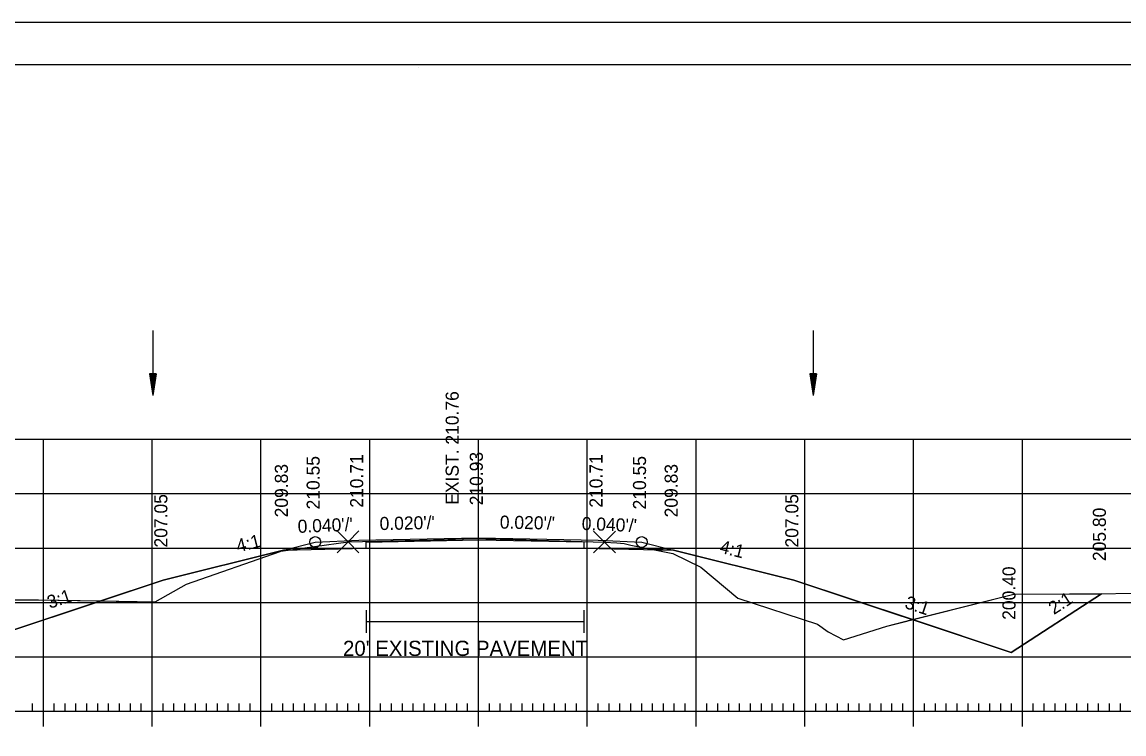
# Model space of a CAD drawing. Extents: x 1312042 to 1371461, y 379929 to 1834241.
# Drawn here: x 1371256.3 to 1371357.6, y 380076.8 to 380142.3 of the extents above; entities that cross this region are included whole.
import ezdxf

# ---------------------------------------------------------------- set-up
doc = ezdxf.new("R2010")
doc.units = 0
for name, color, linetype in [('Default', 7, 'Continuous'), ('R_Alt Surface', 7, 'Continuous'), ('R_Axis', 7, 'Continuous'), ('R_Axis Annot', 7, 'Continuous'), ('R_Border', 7, 'Continuous'), ('R_Exist Surface', 7, 'Continuous'), ('R_Fin Surface', 7, 'Continuous'), ('R_Grid', 7, 'Continuous'), ('R_No Plot', 7, 'Continuous'), ('R_Water Annot', 7, 'Continuous'), ('R_Xsect Elev', 7, 'Continuous'), ('R_Xsect Slope', 7, 'Continuous')]:
    doc.layers.add(name, color=color, linetype=linetype)

msp = doc.modelspace()

# ---------------------------------------------------------------- linework, layer by layer
at = {"layer": 'Default'}
for p, q in [((1371287.96, 380088.19), (1371287.96, 380086.13)), ((1371307.96, 380088.19), (1371307.96, 380086.13)), ((1371287.96, 380087.16), (1371307.96, 380087.16))]:
    msp.add_line(p, q, dxfattribs=at)
at = {"layer": 'R_Alt Surface'}
msp.add_lwpolyline([(1371280.36, 380093.73), (1371287.96, 380093.89), (1371287.96, 380094.45), (1371298.28, 380094.68), (1371307.96, 380094.47), (1371307.96, 380093.9), (1371316.19, 380093.73)], dxfattribs=at)
at = {"layer": 'R_Axis'}
for p, q in [((1371258.28, 380077.51), (1371258.28, 380080.31)), ((1371268.28, 380077.51), (1371268.28, 380080.31)), ((1371278.28, 380077.51), (1371278.28, 380080.31)), ((1371288.28, 380077.51), (1371288.28, 380080.31)), ((1371298.28, 380077.51), (1371298.28, 380080.31)), ((1371308.28, 380077.51), (1371308.28, 380080.31)), ((1371318.28, 380077.51), (1371318.28, 380080.31)), ((1371328.28, 380077.51), (1371328.28, 380080.31)), ((1371338.28, 380077.51), (1371338.28, 380080.31)), ((1371348.28, 380077.51), (1371348.28, 380080.31)), ((1371158.28, 380078.91), (1371438.28, 380078.91)), ((1371257.28, 380078.91), (1371257.28, 380079.61)), ((1371259.28, 380078.91), (1371259.28, 380079.61)), ((1371260.28, 380078.91), (1371260.28, 380079.61)), ((1371261.28, 380078.91), (1371261.28, 380079.61)), ((1371262.28, 380078.91), (1371262.28, 380079.61)), ((1371263.28, 380078.91), (1371263.28, 380079.61)), ((1371264.28, 380078.91), (1371264.28, 380079.61)), ((1371265.28, 380078.91), (1371265.28, 380079.61)), ((1371266.28, 380078.91), (1371266.28, 380079.61)), ((1371267.28, 380078.91), (1371267.28, 380079.61)), ((1371269.28, 380078.91), (1371269.28, 380079.61)), ((1371270.28, 380078.91), (1371270.28, 380079.61)), ((1371271.28, 380078.91), (1371271.28, 380079.61)), ((1371272.28, 380078.91), (1371272.28, 380079.61)), ((1371273.28, 380078.91), (1371273.28, 380079.61)), ((1371274.28, 380078.91), (1371274.28, 380079.61)), ((1371275.28, 380078.91), (1371275.28, 380079.61)), ((1371276.28, 380078.91), (1371276.28, 380079.61)), ((1371277.28, 380078.91), (1371277.28, 380079.61)), ((1371279.28, 380078.91), (1371279.28, 380079.61)), ((1371280.28, 380078.91), (1371280.28, 380079.61)), ((1371281.28, 380078.91), (1371281.28, 380079.61)), ((1371282.28, 380078.91), (1371282.28, 380079.61)), ((1371283.28, 380078.91), (1371283.28, 380079.61)), ((1371284.28, 380078.91), (1371284.28, 380079.61)), ((1371285.28, 380078.91), (1371285.28, 380079.61)), ((1371286.28, 380078.91), (1371286.28, 380079.61)), ((1371287.28, 380078.91), (1371287.28, 380079.61)), ((1371289.28, 380078.91), (1371289.28, 380079.61)), ((1371290.28, 380078.91), (1371290.28, 380079.61)), ((1371291.28, 380078.91), (1371291.28, 380079.61)), ((1371292.28, 380078.91), (1371292.28, 380079.61)), ((1371293.28, 380078.91), (1371293.28, 380079.61)), ((1371294.28, 380078.91), (1371294.28, 380079.61)), ((1371295.28, 380078.91), (1371295.28, 380079.61)), ((1371296.28, 380078.91), (1371296.28, 380079.61)), ((1371297.28, 380078.91), (1371297.28, 380079.61)), ((1371299.28, 380078.91), (1371299.28, 380079.61)), ((1371300.28, 380078.91), (1371300.28, 380079.61)), ((1371301.28, 380078.91), (1371301.28, 380079.61)), ((1371302.28, 380078.91), (1371302.28, 380079.61)), ((1371303.28, 380078.91), (1371303.28, 380079.61)), ((1371304.28, 380078.91), (1371304.28, 380079.61)), ((1371305.28, 380078.91), (1371305.28, 380079.61)), ((1371306.28, 380078.91), (1371306.28, 380079.61)), ((1371307.28, 380078.91), (1371307.28, 380079.61)), ((1371309.28, 380078.91), (1371309.28, 380079.61)), ((1371310.28, 380078.91), (1371310.28, 380079.61)), ((1371311.28, 380078.91), (1371311.28, 380079.61)), ((1371312.28, 380078.91), (1371312.28, 380079.61)), ((1371313.28, 380078.91), (1371313.28, 380079.61)), ((1371314.28, 380078.91), (1371314.28, 380079.61)), ((1371315.28, 380078.91), (1371315.28, 380079.61)), ((1371316.28, 380078.91), (1371316.28, 380079.61)), ((1371317.28, 380078.91), (1371317.28, 380079.61)), ((1371319.28, 380078.91), (1371319.28, 380079.61)), ((1371320.28, 380078.91), (1371320.28, 380079.61)), ((1371321.28, 380078.91), (1371321.28, 380079.61)), ((1371322.28, 380078.91), (1371322.28, 380079.61)), ((1371323.28, 380078.91), (1371323.28, 380079.61)), ((1371324.28, 380078.91), (1371324.28, 380079.61)), ((1371325.28, 380078.91), (1371325.28, 380079.61)), ((1371326.28, 380078.91), (1371326.28, 380079.61)), ((1371327.28, 380078.91), (1371327.28, 380079.61)), ((1371329.28, 380078.91), (1371329.28, 380079.61)), ((1371330.28, 380078.91), (1371330.28, 380079.61)), ((1371331.28, 380078.91), (1371331.28, 380079.61)), ((1371332.28, 380078.91), (1371332.28, 380079.61)), ((1371333.28, 380078.91), (1371333.28, 380079.61)), ((1371334.28, 380078.91), (1371334.28, 380079.61)), ((1371335.28, 380078.91), (1371335.28, 380079.61)), ((1371336.28, 380078.91), (1371336.28, 380079.61)), ((1371337.28, 380078.91), (1371337.28, 380079.61)), ((1371339.28, 380078.91), (1371339.28, 380079.61)), ((1371340.28, 380078.91), (1371340.28, 380079.61)), ((1371341.28, 380078.91), (1371341.28, 380079.61)), ((1371342.28, 380078.91), (1371342.28, 380079.61)), ((1371343.28, 380078.91), (1371343.28, 380079.61)), ((1371344.28, 380078.91), (1371344.28, 380079.61)), ((1371345.28, 380078.91), (1371345.28, 380079.61)), ((1371346.28, 380078.91), (1371346.28, 380079.61)), ((1371347.28, 380078.91), (1371347.28, 380079.61)), ((1371349.28, 380078.91), (1371349.28, 380079.61)), ((1371350.28, 380078.91), (1371350.28, 380079.61)), ((1371351.28, 380078.91), (1371351.28, 380079.61)), ((1371352.28, 380078.91), (1371352.28, 380079.61)), ((1371353.28, 380078.91), (1371353.28, 380079.61)), ((1371354.28, 380078.91), (1371354.28, 380079.61)), ((1371355.28, 380078.91), (1371355.28, 380079.61)), ((1371356.28, 380078.91), (1371356.28, 380079.61)), ((1371357.28, 380078.91), (1371357.28, 380079.61))]:
    msp.add_line(p, q, dxfattribs=at)
at = {"layer": 'R_Border'}
for p, q in [((1371140.28, 380138.37), (1371456.46, 380138.37)), ((1371292.8, 380138.11), (1371292.8, 380138.11)), ((1371292.8, 380138.11), (1371292.8, 380138.11))]:
    msp.add_line(p, q, dxfattribs=at)
at = {"layer": 'R_Exist Surface'}
msp.add_lwpolyline([(1371251.91, 380089.15), (1371257.83, 380089.15), (1371268.56, 380088.97), (1371271.45, 380090.58), (1371280.05, 380093.6), (1371280.08, 380093.61), (1371280.1, 380093.62), (1371280.11, 380093.62), (1371280.11, 380093.62), (1371286.29, 380094.48), (1371295.45, 380094.71), (1371297.62, 380094.79), (1371301.62, 380094.71), (1371309.86, 380094.46), (1371311, 380094.4), (1371311.66, 380094.33), (1371311.78, 380094.3), (1371312.29, 380094.17), (1371316.15, 380093.42), (1371318.72, 380092.14), (1371322.13, 380089.31), (1371329.43, 380086.91), (1371330.43, 380086.21), (1371331.82, 380085.48), (1371335.82, 380086.74), (1371335.82, 380086.74), (1371335.82, 380086.74), (1371347.49, 380089.66), (1371352.62, 380089.69), (1371369.58, 380089.81)], dxfattribs=at)
at = {"layer": 'R_Fin Surface'}
msp.add_lwpolyline([(1371235.3, 380088.58), (1371248.72, 380084.11), (1371269.28, 380090.96), (1371280.36, 380093.73), (1371283.28, 380094.46), (1371287.28, 380094.62), (1371298.28, 380094.84), (1371309.28, 380094.62), (1371313.28, 380094.46), (1371316.19, 380093.73), (1371327.28, 380090.96), (1371347.24, 380084.31), (1371355.55, 380089.71)], dxfattribs=at)
at = {"layer": 'R_Grid'}
for p, q in [((1371158.28, 380103.91), (1371438.28, 380103.91)), ((1371258.28, 380078.91), (1371258.28, 380103.91)), ((1371268.28, 380078.91), (1371268.28, 380103.91)), ((1371278.28, 380078.91), (1371278.28, 380103.91)), ((1371288.28, 380078.91), (1371288.28, 380103.91)), ((1371298.28, 380078.91), (1371298.28, 380103.91)), ((1371308.28, 380078.91), (1371308.28, 380103.91)), ((1371318.28, 380078.91), (1371318.28, 380103.91)), ((1371328.28, 380078.91), (1371328.28, 380103.91)), ((1371338.28, 380078.91), (1371338.28, 380103.91)), ((1371348.28, 380078.91), (1371348.28, 380103.91)), ((1371158.28, 380098.91), (1371438.28, 380098.91)), ((1371158.28, 380093.91), (1371438.28, 380093.91)), ((1371158.28, 380088.91), (1371438.28, 380088.91)), ((1371158.28, 380083.91), (1371438.28, 380083.91)), ((1371158.28, 380078.91), (1371438.28, 380078.91))]:
    msp.add_line(p, q, dxfattribs=at)
at = {"layer": 'R_No Plot'}
msp.add_line((1371127.88, 380142.26), (1371461.21, 380142.26), dxfattribs=at)
for points in [[(1371127.87, 380142.26), (1371461.21, 380142.26), (1371461.21, 379928.93), (1371127.87, 379928.93)], [(1371374.2, 380138.37), (1371374.2, 380128.49), (1371409.93, 380128.49), (1371409.93, 380125.57), (1371433.13, 380125.57), (1371433.13, 380101.24), (1371456.46, 380101.24), (1371456.46, 379932.91), (1371140.28, 379932.91), (1371140.28, 380138.37)], [(1371263.55, 380089.06), (1371268.56, 380088.97), (1371271.45, 380090.58), (1371280.05, 380093.6), (1371280.08, 380093.61), (1371280.1, 380093.62), (1371280.11, 380093.62), (1371280.11, 380093.62), (1371281.01, 380093.75), (1371280.36, 380093.73), (1371269.28, 380090.96)], [(1371314.34, 380093.77), (1371316.15, 380093.42), (1371318.72, 380092.14), (1371322.13, 380089.31), (1371329.43, 380086.91), (1371330.43, 380086.21), (1371331.82, 380085.48), (1371335.82, 380086.74), (1371335.82, 380086.74), (1371338.17, 380087.33), (1371327.28, 380090.96), (1371316.19, 380093.73)], [(1371235.3, 380088.58), (1371240.97, 380088.71), (1371251.91, 380089.15), (1371257.83, 380089.15), (1371263.55, 380089.06), (1371248.72, 380084.11)], [(1371338.17, 380087.33), (1371347.49, 380089.66), (1371352.62, 380089.69), (1371355.55, 380089.71), (1371347.24, 380084.31)]]:
    msp.add_lwpolyline(points, close=True, dxfattribs=at)
for points in [[(1371286.29, 380094.48), (1371285.29, 380095.48), (1371286.29, 380094.48), (1371285.29, 380093.48), (1371286.29, 380094.48), (1371287.29, 380093.48), (1371286.29, 380094.48), (1371287.29, 380095.48)], [(1371309.86, 380094.46), (1371308.86, 380095.46), (1371309.86, 380094.46), (1371308.86, 380093.46), (1371309.86, 380094.46), (1371310.86, 380093.46), (1371309.86, 380094.46), (1371310.86, 380095.46)]]:
    msp.add_lwpolyline(points, dxfattribs=at)
for centre in [(1371283.28, 380094.46), (1371313.28, 380094.46)]:
    msp.add_circle(centre, 0.5, dxfattribs=at)
at = {"layer": 'R_Water Annot'}
for p, q in [((1371268.34, 380113.92), (1371268.34, 380107.92)), ((1371329.05, 380113.92), (1371329.05, 380107.92)), ((1371268.04, 380109.92), (1371268.34, 380107.92)), ((1371268.64, 380109.92), (1371268.04, 380109.92)), ((1371268.09, 380109.92), (1371268.34, 380108.25)), ((1371268.14, 380109.92), (1371268.34, 380108.59)), ((1371268.19, 380109.92), (1371268.34, 380108.93)), ((1371268.25, 380109.92), (1371268.34, 380109.27)), ((1371268.3, 380109.92), (1371268.34, 380109.6)), ((1371268.64, 380109.92), (1371268.34, 380107.92)), ((1371268.44, 380109.92), (1371268.34, 380109.27)), ((1371268.54, 380109.92), (1371268.34, 380108.59)), ((1371268.59, 380109.92), (1371268.34, 380108.25)), ((1371268.49, 380109.92), (1371268.34, 380108.93)), ((1371268.39, 380109.92), (1371268.34, 380109.6)), ((1371328.75, 380109.92), (1371329.05, 380107.92)), ((1371329.35, 380109.92), (1371328.75, 380109.92)), ((1371328.8, 380109.92), (1371329.05, 380108.25)), ((1371328.85, 380109.92), (1371329.05, 380108.59)), ((1371328.9, 380109.92), (1371329.05, 380108.93)), ((1371328.95, 380109.92), (1371329.05, 380109.27)), ((1371329, 380109.92), (1371329.05, 380109.6)), ((1371329.35, 380109.92), (1371329.05, 380107.92)), ((1371329.15, 380109.92), (1371329.05, 380109.27)), ((1371329.25, 380109.92), (1371329.05, 380108.59)), ((1371329.3, 380109.92), (1371329.05, 380108.25)), ((1371329.2, 380109.92), (1371329.05, 380108.93)), ((1371329.1, 380109.92), (1371329.05, 380109.6))]:
    msp.add_line(p, q, dxfattribs=at)

# ---------------------------------------------------------------- texts
at = {"layer": 'R_Axis Annot'}
msp.add_text("20' EXISTING PAVEMENT", height=1.4, dxfattribs=at).set_placement((1371285.83, 380083.99))
at = {"layer": 'R_Xsect Elev'}
for s, p in [('EXIST. 210.76', (1371296.46, 380097.89)), ('210.55', (1371283.68, 380097.46)), ('210.71', (1371287.68, 380097.62)), ('210.93', (1371298.68, 380097.84)), ('210.71', (1371309.68, 380097.62)), ('210.55', (1371313.68, 380097.46)), ('209.83', (1371280.76, 380096.73)), ('209.83', (1371316.59, 380096.73)), ('207.05', (1371269.68, 380093.96)), ('207.05', (1371327.68, 380093.96)), ('205.80', (1371355.95, 380092.71)), ('200.40', (1371347.64, 380087.31))]:
    msp.add_text(s, height=1.2, rotation=90, dxfattribs=at).set_placement(p)
at = {"layer": 'R_Xsect Slope'}
for s, rotation, p in [("0.040'/'", 2.2906, (1371281.68, 380095.3)), ("0.020'/'", 1.1458, (1371289.2, 380095.56)), ("0.020'/'", 358.8542, (1371300.23, 380095.7)), ("0.040'/'", 357.7094, (1371307.75, 380095.58)), ('4:1', 14.0362, (1371276.18, 380093.5)), ('4:1', 345.9638, (1371320.37, 380093.5)), ('3:1', 18.4349, (1371258.87, 380088.32)), ('3:1', 341.5651, (1371337.38, 380088.42)), ('2:1', 33.0239, (1371351.17, 380087.74))]:
    msp.add_text(s, height=1.2, rotation=rotation, dxfattribs=at).set_placement(p)

doc.saveas('drawing.dxf')
